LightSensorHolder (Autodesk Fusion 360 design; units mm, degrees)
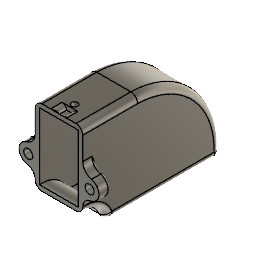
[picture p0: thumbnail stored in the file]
parameter "lageurPCB45mm" = 45
parameter "LongueurPCB16mm" = 16
sketch "Sketch1" plane through (0, 0, 0) normal (1, 0, 0) x axis (0, 1, 0)
  line L1 (75.5782, 28.7396) -> (25.5782, 28.7396)
  line L2 (15, 50.0353) -> (15, 36.7031)
  line L3 (15, 70.0353) -> (15, 50.0353)
  line L4 (39.1347, 70.0353) -> (15, 70.0353)
  arc A1 centre (16.1357, 27.2042) radius 9.5666 clockwise from (15, 36.7031) to (25.5782, 28.7396)
  arc A2 centre (38.2748, 32.5479) radius 37.4973 clockwise from (39.1347, 70.0353) to (75.5782, 28.7396)
  point P2 (25.5782, 28.7396)
  point P3 (75.5782, 28.7396)
  point P6 (15, 50.0353)
  point P7 (15, 70.0353)
  horizontal L1
  vertical L2
  parallel L2 L3
  perpendicular L3 L4
  dimension "d3" distance P2 P3 = 50 (= "lageurPCB45mm + 5 mm")
  dimension "d4" distance P6 P7 = 20
  dimension "d10" diameter P2 = 2.8
extrude "Extrude1" new body sketch "Sketch1" along normal blind 21 (= "LongueurPCB16mm + 5 mm")
shell "Shell1" innerThickness 2
sketch "Sketch2" plane through (0, 0, 28.7396) normal (0, 0, -1) x axis (1, 0, 0)
  line L1 (0, -75.5782) -> (0, -25.5782)
  line L2 (21, -75.5782) -> (0, -75.5782)
  line L3 (21, -25.5782) -> (21, -75.5782)
  line L4 (0, -25.5782) -> (21, -25.5782)
  line L5 (10, -74) -> (2, -74)
  line L6 (10, -53) -> (10, -74)
  line L7 (2, -53) -> (10, -53)
  line L8 (2, -74) -> (2, -53)
  perpendicular L1 L5
  perpendicular L5 L6
  perpendicular L6 L7
  perpendicular L5 L8
extrude "Extrude2" cut sketch "Sketch2" profile of L5 L6 L7 L8 against normal blind 2
sketch "Sketch3" plane through (0, 0, 70.0353) normal (0, 0, 1) x axis (-1, 0, 0)
  line L1 (0, -15) -> (0, -39.1347)
  line L2 (-21, -15) -> (0, -15)
  line L3 (-21, -39.1347) -> (-21, -15)
  line L4 (0, -39.1347) -> (-21, -39.1347)
  line L5 (-8.8461, -20) -> (-11.8461, -20)
  line L6 (-8.8461, -17) -> (-8.8461, -20)
  line L7 (-11.8461, -17) -> (-8.8461, -17)
  line L8 (-11.8461, -20) -> (-11.8461, -17)
  circle C1 centre (-10.4, -22) radius 1.4
  perpendicular L5 L6
  perpendicular L6 L7
  perpendicular L5 L8
  dimension "d10" diameter C1 = 2.8
extrude "Extrude3" cut sketch "Sketch3" profile of C1 L5 L6 L7 L8 against normal blind 2
fillet "Fillet1" radius 3
fillet "Fillet2" radius 2
fillet "Fillet3" radius 2
fillet "Fillet4" radius 3
fillet "Fillet5" radius 1.4
fillet "Fillet6" radius 2
fillet "Fillet7" radius 1.9
fillet "Fillet8" radius 3
sketch "Sketch4" plane through (0, 15, 0) normal (0, -1, 0) x axis (1, 0, 0)
  line L1 (19, 68.0353) -> (2, 68.0353)
  line L2 (19, 38.7149) -> (19, 68.0353)
  line L3 (2, 38.7149) -> (19, 38.7149)
  line L4 (2, 68.0353) -> (2, 38.7149)
  curve K1 (18, 36.7031) -> (21, 39.7193)
  line L5 (21, 67.0353) -> (21, 39.7193)
  line L6 (13.8461, 70.0353) -> (18, 70.0353)
  line L7 (0, 39.7193) -> (0, 67.0353)
  curve K2 (0, 39.7193) -> (3, 36.7031)
  line L8 (18, 36.7031) -> (3, 36.7031)
  line L9 (1, 46) -> (1, 50)
  line L10 (20, 50) -> (20, 46)
  line L11 (6.8461, 70.0353) -> (13.8461, 70.0353)
  line L12 (3, 70.0353) -> (6.8461, 70.0353)
  arc A1 centre (18, 67.0353) radius 3 clockwise from (18, 70.0353) to (21, 67.0353)
  arc A2 centre (3, 67.0353) radius 3 clockwise from (0, 67.0353) to (3, 70.0353)
  circle C1 centre (-3, 48) radius 2
  circle C2 centre (24, 48) radius 2
  arc A3 centre (23.8125, 48) radius 4.3052 clockwise from (20, 50) to (20, 46)
  arc A4 centre (-2.8125, 48) radius 4.3052 clockwise from (1, 46) to (1, 50)
  parallel L4 L9
  parallel L2 L10
  dimension "d21" diameter C1 = 4
  dimension "d22" diameter C2 = 4
extrude "Extrude4" add sketch "Sketch4" profile of L5 L7 C1 C2 A3 A4 against normal blind 5
fillet "Fillet9" radius 5
fillet "Fillet10" radius 4
fillet "Fillet11" radius 4
fillet "Fillet12" radius 5
fillet "Fillet13" radius 1
fillet "Fillet14" radius 1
